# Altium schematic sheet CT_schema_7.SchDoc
size 287 x 160 mm
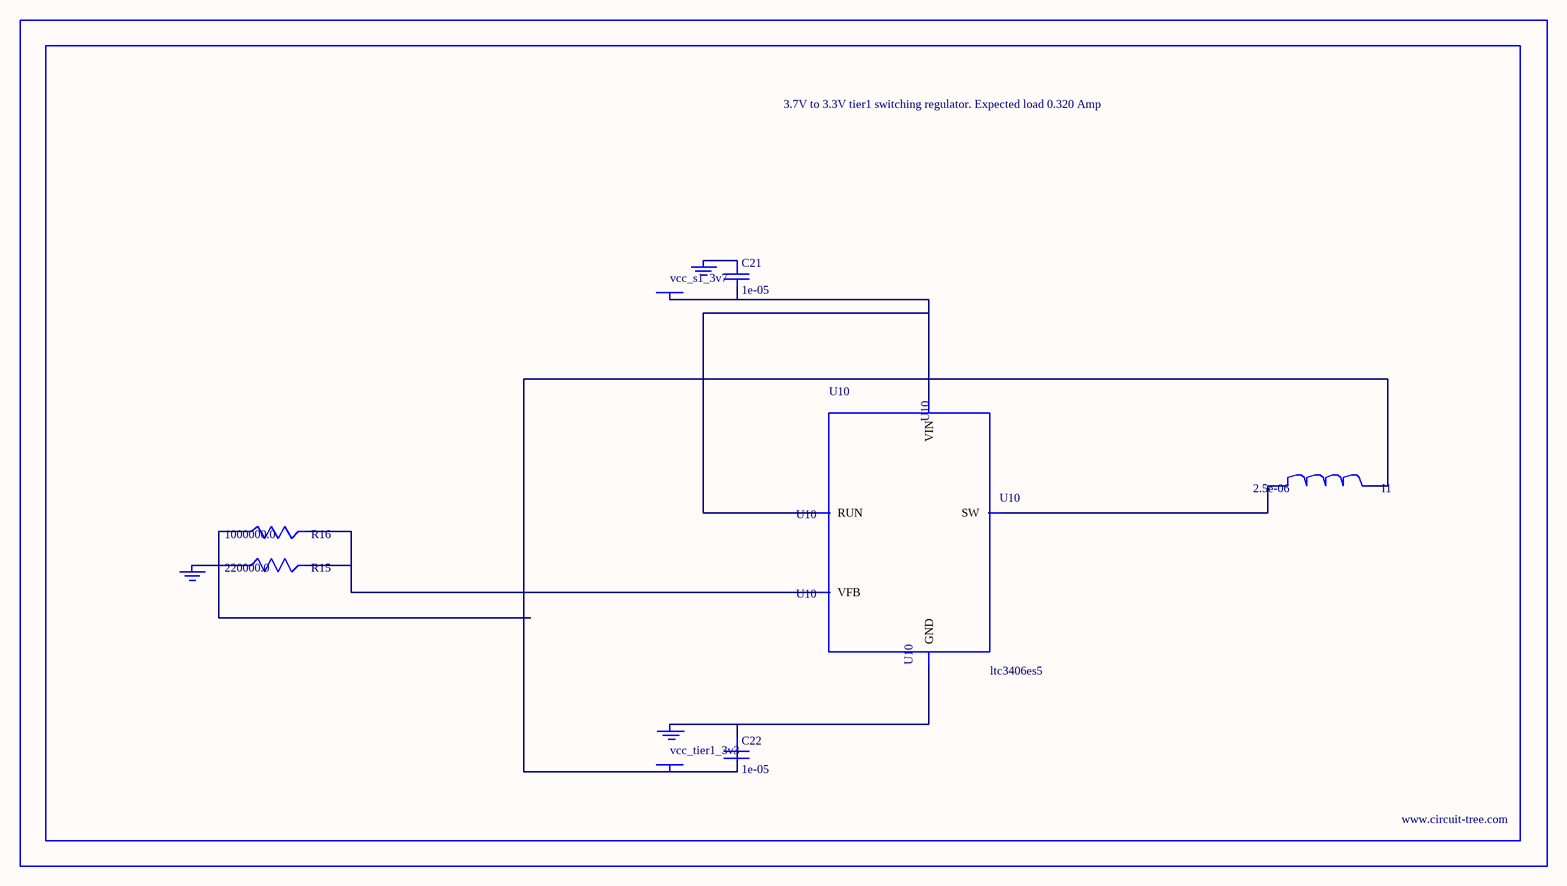
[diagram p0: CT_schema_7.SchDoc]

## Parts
BORDER6  (no value)
C21  1e-05  [C0805]
C22  1e-05  [C0805]
GND_INSTANCE_6_0  (no value)
GND_INSTANCE_6_1  (no value)
GND_INSTANCE_6_2  (no value)
I1  2.5e-06  [DR1040]
POWER_INSTANCE_6_0  vcc_tier1_3v3
POWER_INSTANCE_6_1  vcc_s1_3v7
R15  220000.0  [R0603]
R16  1000000.0  [R0603]
U10  ltc3406es5  [TSOT-23-5]

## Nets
NetC21_1: C21.1 GND_INSTANCE_6_1.0(GND)
NetC21_2: C21.2 POWER_INSTANCE_6_1.0(PWR) U10.1(RUN) U10.4(VIN)
NetC22_1: C22.1 GND_INSTANCE_6_0.0(GND) U10.2(GND)
NetC22_2: C22.2 I1.2 POWER_INSTANCE_6_0.0(PWR) R16.1
NetGND_INSTANCE_6_2_0: GND_INSTANCE_6_2.0(GND) R15.1
NetI1_1: I1.1 U10.3(SW)
NetR15_2: R15.2 R16.2 U10.5(VFB)

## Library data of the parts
BORDER6 = BORDER_PAGE6
C21 C22 = C0805C106K8RACTU
GND_INSTANCE_6_0-GND_INSTANCE_6_2 = GND
I1 = DR1040-2R5-R
POWER_INSTANCE_6_0 POWER_INSTANCE_6_1 = PWR
R15 = RC0603JR-07220KL
R16 = RC0603JR-071ML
